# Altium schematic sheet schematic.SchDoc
size A
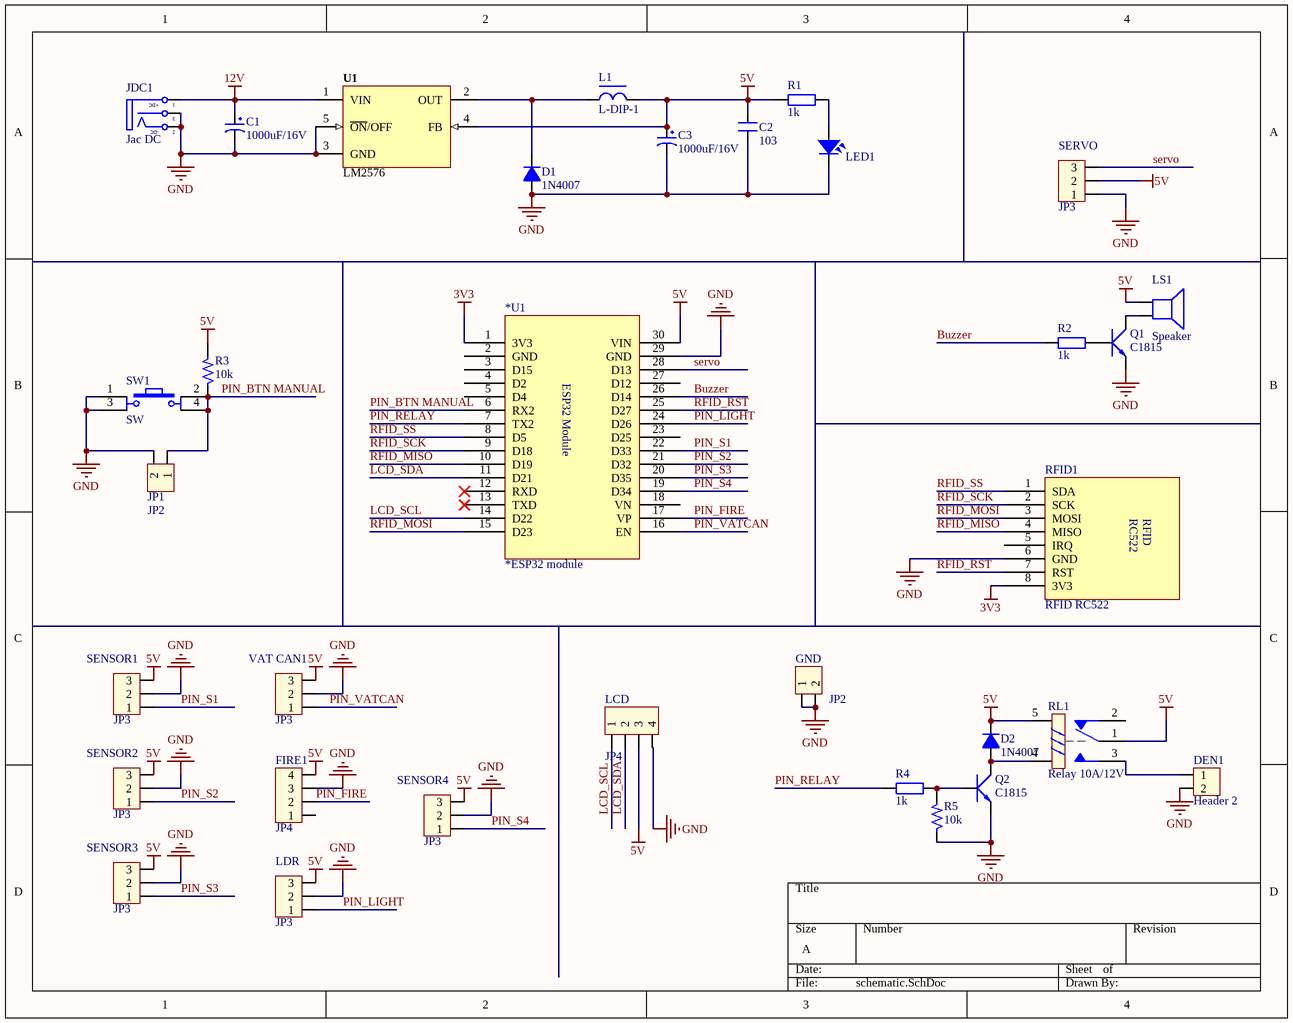
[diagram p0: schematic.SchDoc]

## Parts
*U1  *ESP32 module  [ESP32 Module 30PIN]
C1  1000uF/16V  [CP1.5/3.4]
C2  103  [CN1.5]
C3  1000uF/16V  [CP1.5/3.4]
D1  1N4007  [D1A]
D2  1N4007  [DIO-SMD-106]
DEN1  Header 2  [HED2]
FIRE1  JP4  [CON4]
GND  JP2  [CON2]
JDC1  Jac DC  [DC0]
JP1  JP2  [CON2]
L1  L-DIP-1  [L-DIP-M-9.5x5.5]
LCD  JP4  [CON4]
LDR  JP3  [CON3]
LED1  LED  [LED-5-Green]  (value not drawn)
LS1  Speaker  [SPEAKER]
Q1  C1815  [QTO-92]
Q2  C1815  [QTO-92]
R1  1k  [R1/4W]
R2  1k  [R1/4W]
R3  10k  [SM-RES-1206]
R4  1k  [R1/4W]
R5  10k  [SM-RES-1206]
RFID1  RFID RC522  [JP8]
RL1  Relay 10A/12V  [RL_SPDT_10A]
SENSOR1  JP3  [CON3]
SENSOR2  JP3  [CON3]
SENSOR3  JP3  [CON3]
SENSOR4  JP3  [CON3]
SERVO  JP3  [CON3]
SW1  SW  [SW4]
U1  LM2576  [DIP5-T]
VAT_CAN1  JP3  [CON3]

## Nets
3V3: *U1.1(3V3) RFID1.8(3V3)
5V: *U1.30(VIN) C2.2 C3.1 D2.2(K) FIRE1.4 L1.2 LCD.3 LDR.3 LS1.1 R1.1 R3.2 RL1.1 RL1.5 SENSOR1.3 SENSOR2.3 SENSOR3.3 SENSOR4.3 SERVO.2 U1.4(FB) VAT_CAN1.3
12V: C1.1 JDC1.1(T) U1.1(VIN)
GND: *U1.29(GND) C1.2 C2.1 C3.2 D1.1(A) DEN1.2 FIRE1.3 GND.1 GND.2 JDC1.2(TN) JDC1.3(S) JP1.2 LCD.4 LDR.2 LED1.2 Q1.1(E) Q2.1(E) R5.1 RFID1.6(GND) SENSOR1.2 SENSOR2.2 SENSOR3.2 SENSOR4.2 SERVO.1 SW1.1 SW1.3 U1.3(GND) U1.5(~{ON}/OFF) VAT_CAN1.2
Buzzer: *U1.26(D14) R2.1
LCD_SCL: *U1.14(D22) LCD.1
LCD_SDA: *U1.11(D21) LCD.2
PIN_BTN MANUAL: *U1.6(RX2) JP1.1 R3.1 SW1.2 SW1.4
PIN_FIRE: *U1.17(VP) FIRE1.2
PIN_LIGHT: *U1.24(D26) LDR.1
PIN_RELAY: *U1.7(TX2) R4.1
PIN_S1: *U1.22(D33) SENSOR1.1
PIN_S2: *U1.21(D32) SENSOR2.1
PIN_S3: *U1.20(D35) SENSOR3.1
PIN_S4: *U1.19(D34) SENSOR4.1
PIN_VATCAN: *U1.16(EN) VAT_CAN1.1
RFID_MISO: *U1.10(D19) RFID1.4(MISO)
RFID_MOSI: *U1.15(D23) RFID1.3(MOSI)
RFID_RST: *U1.25(D27) RFID1.7(RST)
RFID_SCK: *U1.9(D18) RFID1.2(SCK)
RFID_SS: *U1.8(D5) RFID1.1(SDA)
servo: *U1.28(D13) SERVO.3
NetD1_2: D1.2(K) L1.1 U1.2(OUT)
NetD2_1: D2.1(A) Q2.2(C) RL1.4
NetDEN1_1: DEN1.1 RL1.3
NetLED1_1: LED1.1 R1.2
NetLS1_2: LS1.2 Q1.2(C)
NetQ1_3: Q1.3(B) R2.2
NetQ2_3: Q2.3(B) R4.2 R5.2

Not connected (* = marked no-connect by the designer): *U1 2(GND) 3(D15) 4(D2) 5(D4) 12(RXD)* 13(TXD)* 18(VN) 23(D25) 27(D12); FIRE1 1; RFID1 5(IRQ); RL1 2

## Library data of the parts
*U1 = ESP32 module
C1 C3 = CP4: Cap 1000uF/16V - 220uF/50V; Description 5: 4,7uF>10uF/250V_3,3uF>10uF/400V - 2,2uF>4,7uF/450V; Description 1: 2200uF-3300uF/6,3V - 1000uF-2200uF/10V; Description 2: 1000uF/16V - 470uF => 1000uF/25V - 100uF/100V; Description 3: 330uF>470uF/35V_220uF>470uF/50V_10uF>22uF/250V; Description 4: 220uF => 330uF/63V - 10uF =>33uF/160 - 200V
C2 = CN1.5: Cap np 682pF => 104pF; Value: 0.01uF
D1 D2 = D1A: Diode 1A
DEN1 = Hed2: Header 2 (Green)
FIRE1 LCD = Con4: Connector 4
GND JP1 = Con2: Connector 2
JDC1 = DCIN: Jac DC input
L1 = L-DIP-1: Inductor; Value: 150 mH
LDR SENSOR1-SENSOR4 SERVO VAT_CAN1 = Con3: Connector 3
LED1 = LED: LED Single colour Green and Red; Value: LED 3 ly Single Colour
LS1 = Speaker: Loudspeaker
Q1 Q2 = C1815: NPN 600mW, ECB
R1 R2 R4 = R1/4W: Resistor 1/4W; Value: R1/4W - 1K
R3 R5 = R: Resistor 1/4W; Value: R1/4W - 1K
RL1 = Relay 1: Relay SPDT,10A - 12VDC 5 Pin; Value: Relay SPDT, 10A, 12V
SW1 = SW4: Switch button 4 pin; Value: Button chip 4 pin
U1 = LM2576: Max Input Voltage: 12 V; Max Output Current: 3 (6.0 peak) A; Max Output Voltage: mV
